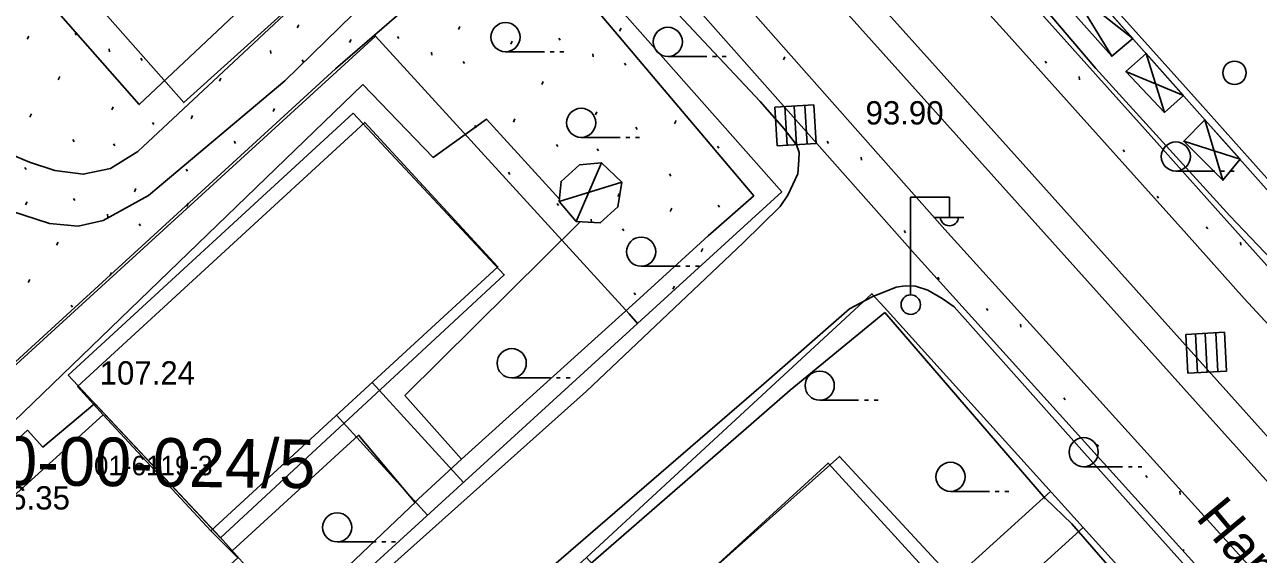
# Model space of a CAD drawing. Extents: x 412225 to 413380, y 4456471 to 4457189.
# Drawn here: x 412650.9 to 412714.4, y 4457101.8 to 4457129.1 of the extents above; entities that cross this region are included whole.
import ezdxf

# ---------------------------------------------------------------- set-up
doc = ezdxf.new("R2010")
doc.units = 0
for name, color, linetype in [('0_HALİHAZIR', 7, 'Continuous'), ('0_KADASTRO', 7, 'Continuous'), ('Level 27', 7, 'Continuous'), ('Level 41', 7, 'Continuous'), ('Level 46', 7, 'Continuous'), ('Level 56', 7, 'Continuous'), ('Level 57', 7, 'Continuous'), ('Level 59', 7, 'Continuous'), ('Level 62', 7, 'Continuous')]:
    doc.layers.add(name, color=color, linetype=linetype)

msp = doc.modelspace()

# ---------------------------------------------------------------- linework, layer by layer
at = {"layer": '0_HALİHAZIR'}
for p, q in [((412706.818, 4457127.443), (412702.699, 4457134.216)), ((412707.902, 4457128.36), (412701.531, 4457133.384)), ((412675.629, 4457127.674), (412677.629, 4457127.674)), ((412677.929, 4457127.674), (412678.129, 4457127.674)), ((412678.429, 4457127.674), (412678.629, 4457127.674)), ((412709.534, 4457124.554), (412708.592, 4457127.582)), ((412683.981, 4457127.427), (412685.981, 4457127.428)), ((412686.281, 4457127.428), (412686.481, 4457127.428)), ((412686.781, 4457127.428), (412686.981, 4457127.428)), ((412710.517, 4457125.415), (412707.551, 4457126.656)), ((412691.486, 4457124.94), (412689.49, 4457124.82)), ((412691.486, 4457124.94), (412689.49, 4457124.82)), ((412689.49, 4457124.82), (412689.61, 4457122.824)), ((412689.49, 4457124.82), (412689.61, 4457122.824)), ((412690.114, 4457122.854), (412689.994, 4457124.85)), ((412690.608, 4457122.884), (412690.488, 4457124.88)), ((412691.155, 4457122.916), (412691.035, 4457124.913)), ((412691.606, 4457122.944), (412691.486, 4457124.94)), ((412691.606, 4457122.944), (412691.486, 4457124.94)), ((412712.543, 4457121.066), (412711.618, 4457124.176)), ((412679.524, 4457123.267), (412681.524, 4457123.267)), ((412681.824, 4457123.267), (412682.024, 4457123.267)), ((412682.324, 4457123.267), (412682.524, 4457123.267)), ((412689.61, 4457122.824), (412691.606, 4457122.944)), ((412689.61, 4457122.824), (412691.606, 4457122.944)), ((412710.53, 4457123.072), (412713.428, 4457122.139)), ((412680.568, 4457121.961), (412679.264, 4457118.937)), ((412710.119, 4457121.531), (412712.119, 4457121.531)), ((412712.419, 4457121.531), (412712.619, 4457121.531)), ((412712.919, 4457121.531), (412713.119, 4457121.531)), ((412678.393, 4457119.97), (412681.611, 4457120.956)), ((412696.469, 4457115.192), (412696.469, 4457120.192)), ((412696.469, 4457120.192), (412698.469, 4457120.192)), ((412698.469, 4457119.192), (412698.469, 4457120.192)), ((412697.709, 4457119.152), (412699.209, 4457119.152)), ((412682.607, 4457116.638), (412684.607, 4457116.638)), ((412684.907, 4457116.638), (412685.107, 4457116.638)), ((412685.407, 4457116.638), (412685.607, 4457116.638)), ((412712.624, 4457113.242), (412710.627, 4457113.136)), ((412712.624, 4457113.242), (412710.627, 4457113.136)), ((412710.627, 4457113.136), (412710.732, 4457111.139)), ((412710.627, 4457113.136), (412710.732, 4457111.139)), ((412711.236, 4457111.166), (412711.131, 4457113.163)), ((412711.731, 4457111.192), (412711.625, 4457113.189)), ((412712.278, 4457111.221), (412712.172, 4457113.218)), ((412712.729, 4457111.244), (412712.624, 4457113.242)), ((412712.729, 4457111.244), (412712.624, 4457113.242)), ((412710.732, 4457111.139), (412712.729, 4457111.244)), ((412710.732, 4457111.139), (412712.729, 4457111.244)), ((412675.948, 4457110.902), (412677.948, 4457110.902)), ((412678.248, 4457110.902), (412678.448, 4457110.902)), ((412678.748, 4457110.902), (412678.948, 4457110.902)), ((412691.797, 4457109.75), (412693.797, 4457109.75)), ((412694.097, 4457109.75), (412694.297, 4457109.75)), ((412694.597, 4457109.75), (412694.797, 4457109.75)), ((412705.376, 4457106.329), (412707.376, 4457106.329)), ((412707.676, 4457106.329), (412707.876, 4457106.329)), ((412708.176, 4457106.329), (412708.376, 4457106.329)), ((412698.527, 4457105.06), (412700.527, 4457105.06)), ((412700.827, 4457105.06), (412701.027, 4457105.06)), ((412701.327, 4457105.06), (412701.527, 4457105.06)), ((412666.966, 4457102.463), (412668.966, 4457102.463)), ((412669.266, 4457102.463), (412669.466, 4457102.463)), ((412669.766, 4457102.463), (412669.966, 4457102.463))]:
    msp.add_line(p, q, dxfattribs=at)
for points in [[(412705.989, 4457175.902), (412708.685, 4457167.247), (412713.393, 4457152.179), (412718.466, 4457135.96), (412723.01, 4457121.497), (412723.233, 4457119.951), (412723.225, 4457119.111), (412722.926, 4457118.055), (412722.372, 4457117.245), (412721.653, 4457116.54), (412720.698, 4457115.75), (412719.698, 4457115.036), (412718.765, 4457114.671), (412717.963, 4457114.689), (412717.233, 4457114.935), (412716.493, 4457115.461), (412712.894, 4457119.231)], [(412760.597, 4457057.302), (412737.807, 4457082.507), (412725.053, 4457096.478), (412702.86, 4457121.225), (412684.495, 4457141.69), (412664.069, 4457164.396), (412656.447, 4457172.689), (412655.87, 4457173.073), (412655.68, 4457173.156), (412655.425, 4457173.169), (412655.248, 4457173.057), (412654.964, 4457172.743), (412654.909, 4457172.624), (412654.897, 4457172.394), (412654.966, 4457172.098), (412655.043, 4457171.935), (412663.395, 4457162.69), (412677.972, 4457146.589), (412692.658, 4457130.251), (412716.693, 4457103.495), (412730.446, 4457088.387), (412748.495, 4457068.401), (412760.853, 4457054.305)], [(412666.722, 4457149.847), (412683.715, 4457130.465), (412688.733, 4457125.108), (412689.962, 4457123.702), (412690.595, 4457122.882), (412690.735, 4457122.493), (412690.726, 4457122.1), (412690.676, 4457121.39), (412690.163, 4457120.297), (412689.764, 4457119.716), (412687.857, 4457117.849), (412679.792, 4457110.22), (412668.162, 4457099.827), (412652.892, 4457085.728), (412650.071, 4457083.307)], [(412712.894, 4457119.231), (412706.001, 4457126.816), (412694.192, 4457140.701), (412685.594, 4457149.898)], [(412664.042, 4457148.037), (412672.376, 4457138.915), (412662.818, 4457130.641), (412656.783, 4457124.956), (412641.01, 4457142.85), (412643.209, 4457144.758)], [(412674.777, 4457136.425), (412664.275, 4457126.179), (412657.254, 4457120.279), (412654.933, 4457118.989), (412653.64, 4457118.705), (412652.173, 4457118.831), (412650.162, 4457119.485)], [(412666.876, 4457126.785), (412672.032, 4457131.249), (412676.082, 4457134.847), (412688.401, 4457120.265), (412686.052, 4457118.198), (412682.341, 4457114.814), (412673.365, 4457106.716)], [(412636.89, 4457129.185), (412639.421, 4457128.686), (412641.594, 4457128.096), (412643.378, 4457127.758), (412644.388, 4457127.291), (412645.679, 4457126.37), (412646.785, 4457125.411), (412647.716, 4457124.363), (412648.493, 4457123.616), (412649.171, 4457123.093), (412650.158, 4457122.408), (412651.134, 4457121.991), (412652.439, 4457121.569), (412653.902, 4457121.37), (412655.306, 4457121.661), (412656.704, 4457122.549), (412667.092, 4457132.24)], [(412656.443, 4457091.342), (412647.227, 4457082.781), (412640.333, 4457090.585), (412634.547, 4457097.223), (412666.876, 4457126.785)], [(412668.291, 4457125.985), (412636.342, 4457095.163)], [(412668.284, 4457125.992), (412671.908, 4457122.233), (412674.643, 4457124.207), (412678.403, 4457120.085)], [(412679.474, 4457118.926), (412670.455, 4457109.991)], [(412693.328, 4457114.453), (412694.492, 4457115.068), (412695.736, 4457115.568), (412696.195, 4457115.629), (412696.723, 4457115.614), (412697.364, 4457115.408), (412698.092, 4457114.988), (412698.72, 4457114.549), (412707.799, 4457104.353), (412723.362, 4457087.002), (412735.509, 4457073.348), (412743.255, 4457064.858), (412750.684, 4457056.25)], [(412688.789, 4457110.474), (412693.328, 4457114.453)], [(412690.277, 4457110.274), (412695.139, 4457114.254)], [(412703.417, 4457104.688), (412695.139, 4457114.254)], [(412688.789, 4457110.474), (412676.857, 4457100.196), (412663.153, 4457087.564), (412650.553, 4457076.263), (412642.59, 4457068.703), (412641.23, 4457067.176), (412640.87, 4457066.641), (412640.687, 4457065.987), (412640.751, 4457065.319), (412641.497, 4457064.308), (412651.959, 4457052.379)], [(412673.361, 4457106.712), (412670.455, 4457109.991)], [(412687.878, 4457108.184), (412690.277, 4457110.274)], [(412670.969, 4457104.5), (412668.071, 4457107.953), (412661.57, 4457102.012)], [(412679.492, 4457100.883), (412687.878, 4457108.184)], [(412673.365, 4457106.716), (412670.934, 4457104.466)], [(412703.412, 4457104.694), (412704.773, 4457103.398)], [(412671.023, 4457104.55), (412664.073, 4457097.928), (412658.723, 4457093.243)], [(412727.108, 4457078.339), (412719.494, 4457087.022), (412710.949, 4457096.289), (412704.773, 4457103.398)]]:
    msp.add_lwpolyline(points, dxfattribs=at)
for points in [[(412697.709, 4457139.833), (412714.317, 4457146.955), (412722.11, 4457122.08), (412716.948, 4457118.177)], [(412707.902, 4457128.36), (412706.818, 4457127.443), (412701.531, 4457133.384), (412702.699, 4457134.216)], [(412710.517, 4457125.415), (412709.534, 4457124.554), (412707.551, 4457126.656), (412708.592, 4457127.582)], [(412667.785, 4457124.52), (412675.565, 4457116.206), (412660.969, 4457102.682), (412653.13, 4457111.036)], [(412713.428, 4457122.139), (412712.543, 4457121.066), (412710.53, 4457123.072), (412711.618, 4457124.176)], [(412678.393, 4457119.97), (412678.484, 4457121), (412679.443, 4457121.862), (412680.568, 4457121.961), (412681.611, 4457120.956), (412681.41, 4457119.688), (412680.503, 4457118.872), (412679.264, 4457118.937)], [(412654.493, 4457109.584), (412651.817, 4457107.339), (412651.035, 4457108.208), (412647.338, 4457104.848), (412648.093, 4457103.7), (412639.667, 4457096.084), (412647.572, 4457087.605), (412662.236, 4457101.272), (412660.946, 4457102.707)], [(412699.306, 4457085.504), (412697.898, 4457084.214), (412684.378, 4457099.346), (412692.812, 4457106.864), (412706.357, 4457092.23)]]:
    msp.add_lwpolyline(points, close=True, dxfattribs=at)
for centre, radius in [((412675.629, 4457128.424), 0.75), ((412683.981, 4457128.177), 0.75), ((412679.524, 4457124.017), 0.75), ((412710.119, 4457122.281), 0.75), ((412682.607, 4457117.388), 0.75), ((412696.479, 4457114.667), 0.5), ((412675.948, 4457111.652), 0.75), ((412691.797, 4457110.5), 0.75), ((412705.376, 4457107.079), 0.75), ((412698.527, 4457105.81), 0.75), ((412666.966, 4457103.213), 0.75)]:
    msp.add_circle(centre, radius, dxfattribs=at)
msp.add_arc((412698.469, 4457119.196), 0.474, 184.83843, 355.14641, dxfattribs=at)
at = {"layer": '0_KADASTRO'}
for points in [[(412704.368, 4457175.985), (412704.699, 4457175.01), (412713.634, 4457148.666), (412727.716, 4457107.15), (412717.329, 4457118.357), (412714.38, 4457121.644), (412711.366, 4457125.004), (412708.214, 4457128.516), (412705.108, 4457131.979), (412702.919, 4457134.419), (412700.803, 4457136.777), (412697.932, 4457139.977), (412668.129, 4457173.196), (412667.455, 4457173.947), (412667.448, 4457174.425), (412667.418, 4457176.412)], [(412602.001, 4457142.229), (412625.676, 4457149.845), (412628.236, 4457150.669), (412623.56, 4457165.205), (412628.608, 4457159.498), (412642.417, 4457143.887), (412658.161, 4457126.088), (412659.073, 4457125.057), (412673.936, 4457138.44), (412689.844, 4457120.47), (412682.426, 4457113.701), (412681.983, 4457114.187), (412668.946, 4457128.476), (412634.964, 4457097.471), (412647.897, 4457083.297), (412648.445, 4457082.697), (412645.49, 4457080.001), (412613.407, 4457115.704)]]:
    msp.add_lwpolyline(points, dxfattribs=at)
for points in [[(412622.112, 4457169.708), (412634.488, 4457173.687), (412637.329, 4457174.618), (412639.978, 4457174.528), (412642.518, 4457173.555), (412644.604, 4457171.572), (412673.936, 4457138.44), (412659.073, 4457125.057), (412658.161, 4457126.088), (412642.417, 4457143.887), (412628.608, 4457159.498), (412623.56, 4457165.205)], [(412634.964, 4457097.471), (412668.946, 4457128.476), (412681.983, 4457114.187), (412682.426, 4457113.701), (412648.445, 4457082.697), (412647.897, 4457083.297)], [(412679.801, 4457101.657), (412694.484, 4457115.229), (412695.104, 4457114.543), (412711.275, 4457096.665), (412726.691, 4457079.62), (412711.883, 4457066.181), (412696.526, 4457083.162), (412680.404, 4457100.989)]]:
    msp.add_lwpolyline(points, close=True, dxfattribs=at)
at = {"layer": 'Level 27'}
for points in [[(412727.716, 4457107.15), (412717.329, 4457118.357), (412714.38, 4457121.644), (412711.366, 4457125.004), (412708.214, 4457128.516), (412705.108, 4457131.979), (412702.919, 4457134.419), (412700.803, 4457136.777), (412697.932, 4457139.977), (412668.129, 4457173.196), (412667.455, 4457173.947), (412667.418, 4457176.412)], [(412642.518, 4457173.555), (412644.604, 4457171.572), (412644.604, 4457171.572), (412673.936, 4457138.44), (412689.844, 4457120.47)], [(412689.844, 4457120.47), (412682.426, 4457113.701), (412648.445, 4457082.697), (412645.49, 4457080.001), (412645.49, 4457080.001), (412630.715, 4457066.521)], [(412641.315, 4457066.687), (412676.859, 4457098.984), (412679.801, 4457101.657), (412694.484, 4457115.229)], [(412694.484, 4457115.229), (412695.104, 4457114.543), (412711.275, 4457096.665), (412726.691, 4457079.62), (412736.14, 4457068.507), (412742.859, 4457060.585)]]:
    msp.add_lwpolyline(points, dxfattribs=at)
at = {"layer": 'Level 41'}
for p, q in [((412664.916, 4457128.898), (412664.988, 4457129.057)), ((412673.208, 4457128.813), (412673.281, 4457128.972)), ((412681.501, 4457128.729), (412681.574, 4457128.887)), ((412651.022, 4457128.312), (412651.096, 4457128.471)), ((412653.49, 4457128.631), (412653.56, 4457128.524)), ((412667.607, 4457128.142), (412667.681, 4457128.301)), ((412670.076, 4457128.462), (412670.146, 4457128.354)), ((412675.9, 4457128.057), (412675.973, 4457128.216)), ((412678.368, 4457128.377), (412678.438, 4457128.269)), ((412655.24, 4457127.822), (412655.257, 4457127.662)), ((412663.533, 4457127.737), (412663.549, 4457127.577)), ((412671.825, 4457127.653), (412671.842, 4457127.492)), ((412680.118, 4457127.568), (412680.134, 4457127.408)), ((412656.865, 4457127.336), (412656.934, 4457127.228)), ((412665.158, 4457127.251), (412665.227, 4457127.143)), ((412673.451, 4457127.166), (412673.519, 4457127.058)), ((412681.743, 4457127.081), (412681.812, 4457126.973)), ((412689.927, 4457127.256), (412690, 4457127.415)), ((412703.394, 4457127.184), (412703.465, 4457127.077)), ((412652.617, 4457126.235), (412652.691, 4457126.394)), ((412660.909, 4457126.15), (412660.983, 4457126.309)), ((412705.152, 4457126.393), (412705.17, 4457126.233)), ((412677.495, 4457125.98), (412677.568, 4457126.14)), ((412651.159, 4457124.312), (412651.232, 4457124.471)), ((412655.373, 4457124.677), (412655.445, 4457124.836)), ((412659.452, 4457124.227), (412659.524, 4457124.386)), ((412663.666, 4457124.592), (412663.737, 4457124.751)), ((412680.251, 4457124.422), (412680.322, 4457124.581)), ((412657.462, 4457124.039), (412657.532, 4457123.933)), ((412674.047, 4457123.87), (412674.117, 4457123.763)), ((412676.037, 4457124.057), (412676.109, 4457124.217)), ((412682.339, 4457123.785), (412682.409, 4457123.678)), ((412684.329, 4457123.972), (412684.402, 4457124.132)), ((412653.367, 4457123.152), (412653.437, 4457123.045)), ((412655.464, 4457122.939), (412655.534, 4457122.831)), ((412661.66, 4457123.067), (412661.73, 4457122.96)), ((412678.245, 4457122.898), (412678.315, 4457122.79)), ((412680.342, 4457122.684), (412680.412, 4457122.576)), ((412686.538, 4457122.813), (412686.608, 4457122.705)), ((412692.171, 4457123.065), (412692.241, 4457122.958)), ((412707.412, 4457122.633), (412707.483, 4457122.527)), ((412693.921, 4457122.256), (412693.937, 4457122.096)), ((412650.897, 4457121.724), (412650.967, 4457121.617)), ((412659.189, 4457121.64), (412659.259, 4457121.532)), ((412675.774, 4457121.47), (412675.844, 4457121.362)), ((412684.067, 4457121.385), (412684.137, 4457121.277)), ((412656.536, 4457120.474), (412656.609, 4457120.632)), ((412650.935, 4457119.802), (412651.009, 4457119.961)), ((412653.403, 4457120.122), (412653.473, 4457120.014)), ((412681.414, 4457120.219), (412681.486, 4457120.377)), ((412709.164, 4457120.251), (412709.235, 4457120.144)), ((412655.153, 4457119.313), (412655.17, 4457119.153)), ((412659.228, 4457119.717), (412659.301, 4457119.876)), ((412678.281, 4457119.867), (412678.351, 4457119.759)), ((412684.105, 4457119.462), (412684.179, 4457119.622)), ((412686.574, 4457119.782), (412686.644, 4457119.675)), ((412656.778, 4457118.826), (412656.847, 4457118.718)), ((412680.031, 4457119.058), (412680.047, 4457118.898)), ((412711.687, 4457118.674), (412711.758, 4457118.567)), ((412681.656, 4457118.571), (412681.725, 4457118.464)), ((412696.143, 4457118.473), (412696.212, 4457118.367)), ((412652.53, 4457117.726), (412652.603, 4457117.885)), ((412685.7, 4457117.386), (412685.774, 4457117.545)), ((412713.445, 4457117.883), (412713.463, 4457117.723)), ((412655.286, 4457116.167), (412655.358, 4457116.327)), ((412651.072, 4457115.802), (412651.145, 4457115.962)), ((412684.242, 4457115.463), (412684.315, 4457115.622)), ((412697.87, 4457116.074), (412697.94, 4457115.966)), ((412682.252, 4457115.275), (412682.322, 4457115.168)), ((412653.28, 4457114.643), (412653.35, 4457114.535)), ((412700.377, 4457114.471), (412700.447, 4457114.363)), ((412702.127, 4457113.662), (412702.143, 4457113.502)), ((412704.348, 4457109.879), (412704.418, 4457109.772)), ((412706.076, 4457107.479), (412706.145, 4457107.371)), ((412708.582, 4457105.876), (412708.652, 4457105.769)), ((412710.332, 4457105.068), (412710.348, 4457104.907)), ((412710.498, 4457101.996), (412710.537, 4457102.081))]:
    msp.add_line(p, q, dxfattribs=at)
at = {"layer": 'Level 46'}
msp.add_circle((412713.138, 4457126.586), 0.6, dxfattribs=at)
at = {"layer": 'Level 57'}
for points in [[(412673.936, 4457138.44), (412659.073, 4457125.057), (412658.161, 4457126.088), (412642.417, 4457143.887), (412628.35, 4457159.79), (412624.874, 4457170.596)], [(412648.445, 4457082.697), (412647.897, 4457083.297), (412634.964, 4457097.471), (412668.946, 4457128.476), (412681.983, 4457114.187), (412682.426, 4457113.701)]]:
    msp.add_lwpolyline(points, dxfattribs=at)
at = {"layer": 'Level 59'}
for p, q in [((412668.77, 4457110.67), (412673.465, 4457105.525)), ((412666.93, 4457108.978), (412671.618, 4457103.84)), ((412698.129, 4457100.046), (412703.677, 4457105.065)), ((412699.815, 4457098.199), (412705.355, 4457103.21))]:
    msp.add_line(p, q, dxfattribs=at)
msp.add_lwpolyline([(412654.923, 4457109.007), (412653.612, 4457110.449), (412668.385, 4457124.033), (412675.236, 4457116.615), (412660.463, 4457103.031)], dxfattribs=at)
for points in [[(412640.103, 4457095.573), (412654.923, 4457109.007), (412660.463, 4457103.031), (412661.853, 4457101.653), (412647.033, 4457088.219)], [(412684.79, 4457099.71), (412692.224, 4457106.514), (412705.721, 4457091.73), (412699.749, 4457086.216), (412698.331, 4457084.929)]]:
    msp.add_lwpolyline(points, close=True, dxfattribs=at)
at = {"layer": 'Level 62'}
for points in [[(412734.256, 4457092.738), (412713.634, 4457114.988), (412710.659, 4457118.305), (412707.645, 4457121.665), (412704.493, 4457125.177), (412701.386, 4457128.64), (412699.198, 4457131.08), (412697.082, 4457133.438), (412694.211, 4457136.638), (412658.434, 4457176.516)], [(412648.117, 4457175.147), (412677.68, 4457141.754), (412698.233, 4457118.537)], [(412646.62, 4457173.821), (412676.183, 4457140.428), (412696.711, 4457117.238)], [(412735.743, 4457094.077), (412715.112, 4457116.336), (412712.148, 4457119.64), (412709.134, 4457123.001), (412705.982, 4457126.513), (412702.875, 4457129.975), (412700.687, 4457132.415), (412698.571, 4457134.774), (412695.7, 4457137.974), (412665.889, 4457171.202)], [(412698.233, 4457118.537), (412714.983, 4457100.019), (412730.451, 4457082.917), (412739.951, 4457071.743), (412751.649, 4457057.951)], [(412696.711, 4457117.238), (412713.5, 4457098.677), (412728.947, 4457081.598), (412738.427, 4457070.448), (412750.124, 4457056.657)]]:
    msp.add_lwpolyline(points, dxfattribs=at)

# ---------------------------------------------------------------- texts
at = {"layer": '0_HALİHAZIR'}
for s, p in [('93.90', (412694.153, 4457123.93)), ('107.24', (412654.746, 4457110.553)), ('106.35', (412648.309, 4457104.13))]:
    msp.add_text(s, height=1.2, dxfattribs=at).set_placement(p)
msp.add_text('Hancý Caddesi', height=2, rotation=309.68324, dxfattribs=at).set_placement((412711.099, 4457103.69))
at = {"layer": '0_KADASTRO'}
msp.add_text('01-6119-3', height=1, dxfattribs=at).set_placement((412654.456, 4457105.891))
msp.add_text('01-6119-3', height=1, dxfattribs=at).set_placement((412654.456, 4457105.891))
at = {"layer": 'Level 56'}
msp.add_text('01-1010-00-024/5', height=2.5, rotation=359.4136, dxfattribs=at).set_placement((412639.254, 4457105.496))

doc.saveas('drawing.dxf')
